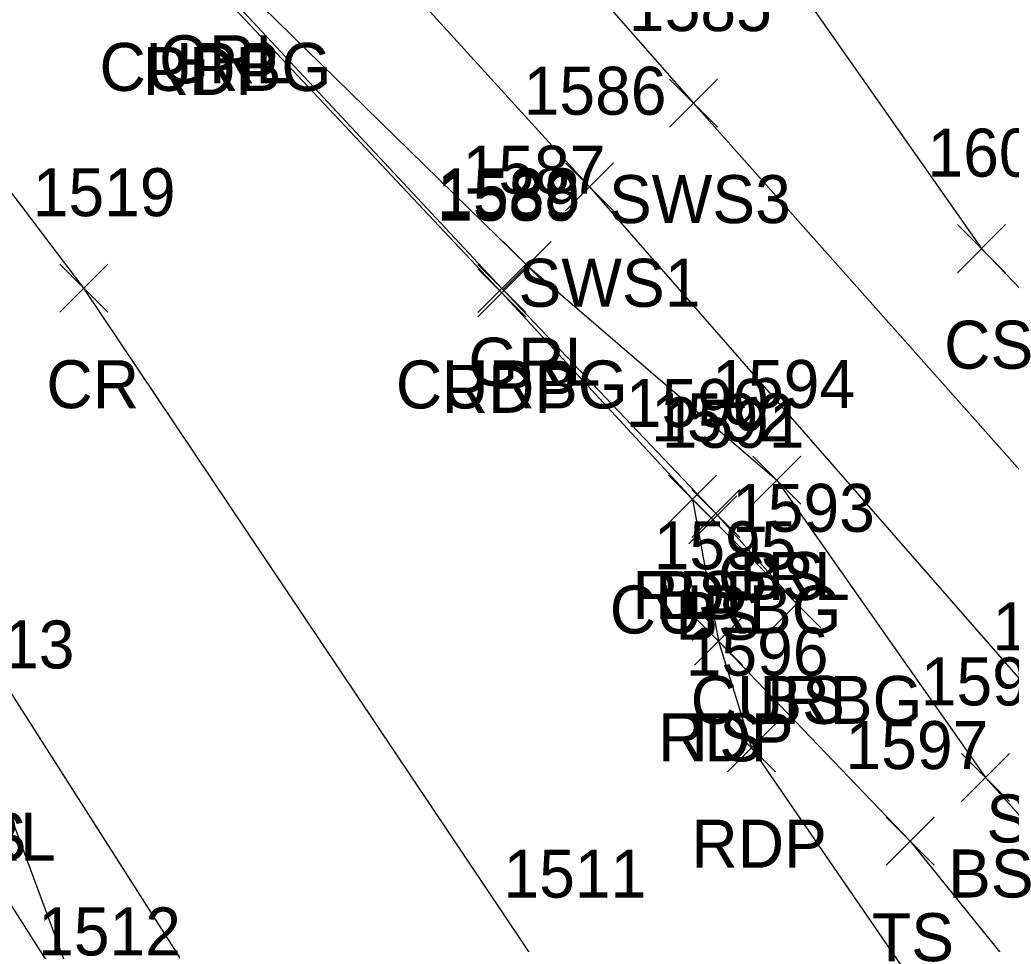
# Model space of a CAD drawing. Extents: x 1499292 to 1501024, y 534584 to 538043.
# Drawn here: x 1499846.53 to 1499887.83, y 537622.77 to 537661.28 of the extents above; entities that cross this region are included whole.
import ezdxf

# ---------------------------------------------------------------- set-up
doc = ezdxf.new("R2010")
doc.units = 0
for name, color, linetype in [('L_A', 7, 'Continuous'), ('L_I', 7, 'Continuous'), ('L_TIC', 7, 'Continuous'), ('LELB', 7, 'Continuous'), ('P_A', 7, 'Continuous'), ('P_I', 7, 'Continuous'), ('P_TIC', 7, 'Continuous'), ('PET', 7, 'Continuous'), ('PRC', 7, 'Continuous'), ('R_A', 7, 'Continuous'), ('R_I', 7, 'Continuous'), ('R_TIC', 7, 'Continuous'), ('RC', 7, 'Continuous'), ('RGR', 7, 'Continuous'), ('RSW', 7, 'Continuous')]:
    doc.layers.add(name, color=color, linetype=linetype)

msp = doc.modelspace()

# ---------------------------------------------------------------- linework, layer by layer
at = {"layer": 'L_TIC'}
for points in [[(1499885.591, 537650.746), (1499887.591, 537652.746)], [(1499887.591, 537650.746), (1499885.591, 537652.746)], [(1499877.067, 537641.108), (1499879.067, 537643.108)], [(1499879.067, 537641.108), (1499877.067, 537643.108)], [(1499873.553, 537640.315), (1499875.553, 537642.315)], [(1499875.553, 537640.315), (1499873.553, 537642.315)], [(1499874.393, 537639.451), (1499876.393, 537641.451)], [(1499876.393, 537639.451), (1499874.393, 537641.451)], [(1499877.892, 537635.949), (1499879.892, 537637.949)], [(1499879.892, 537635.949), (1499877.892, 537637.949)], [(1499874.628, 537634.389), (1499876.628, 537636.389)], [(1499876.628, 537634.389), (1499874.628, 537636.389)], [(1499885.752, 537628.716), (1499887.752, 537630.716)], [(1499887.752, 537628.716), (1499885.752, 537630.716)], [(1499882.617, 537626.063), (1499884.617, 537628.063)], [(1499884.617, 537626.063), (1499882.617, 537628.063)]]:
    msp.add_lwpolyline(points, dxfattribs=at)
at = {"layer": 'LELB'}
for points in [[(1499846.934, 537679.187), (1499854.63, 537681.892), (1499855.345, 537682.192), (1499861.643, 537684.623), (1499869.851, 537675.621), (1499886.591, 537651.746), (1499898.304, 537639.55), (1499906.005, 537630.298), (1499923.982, 537635.989)], [(1499982.952, 537489.682), (1499966.995, 537494.973), (1499951.633, 537501.686), (1499942.165, 537508.923), (1499936.876, 537512.966), (1499930.432, 537522.297), (1499913.696, 537537.042), (1499897.541, 537554.09), (1499883.226, 537576.207), (1499873.982, 537589.177), (1499855.893, 537613.143), (1499849.418, 537619.303), (1499842.663, 537629.916), (1499836.966, 537639.791), (1499825.942, 537654.556), (1499819.306, 537659.466)], [(1499875.628, 537635.389), (1499883.617, 537627.063), (1499893.294, 537615.077), (1499899.95, 537610.946), (1499909.177, 537610.062), (1499915.735, 537611.144), (1499937.582, 537622.682), (1499960.484, 537631.227), (1499993.025, 537642.588), (1500017.771, 537650.353)], [(1499878.067, 537642.108), (1499886.752, 537629.716), (1499900.318, 537614.592), (1499904.837, 537614.724), (1499912.539, 537616.07), (1499937.582, 537622.682)], [(1499874.553, 537641.315), (1499875.393, 537640.451), (1499878.892, 537636.949)]]:
    msp.add_lwpolyline(points, dxfattribs=at)
at = {"layer": 'P_TIC'}
for points in [[(1499848.203, 537649.099), (1499850.203, 537651.099)], [(1499850.203, 537649.099), (1499848.203, 537651.099)], [(1499865.611, 537648.906), (1499867.611, 537650.906)], [(1499867.611, 537648.906), (1499865.611, 537650.906)], [(1499873.553, 537640.315), (1499875.553, 537642.315)], [(1499875.553, 537640.315), (1499873.553, 537642.315)], [(1499874.628, 537634.389), (1499876.628, 537636.389)], [(1499876.628, 537634.389), (1499874.628, 537636.389)], [(1499876.015, 537629.958), (1499878.015, 537631.958)], [(1499878.015, 537629.958), (1499876.015, 537631.958)]]:
    msp.add_lwpolyline(points, dxfattribs=at)
at = {"layer": 'PET'}
msp.add_lwpolyline([(1499898.168, 537558.628), (1499884.724, 537577.025), (1499875.365, 537589.928), (1499858.296, 537614.226), (1499840.479, 537642.142), (1499830.336, 537658.338), (1499824.743, 537665.437), (1499832.024, 537672.415), (1499839.239, 537678.685), (1499843.344, 537674.163), (1499846.686, 537670.947), (1499854.163, 537663.148), (1499866.611, 537649.906), (1499874.553, 537641.315), (1499875.628, 537635.389), (1499877.015, 537630.958), (1499888.962, 537613.552)], dxfattribs=at)
at = {"layer": 'PRC'}
msp.add_lwpolyline([(1500278.962, 537330.133), (1500245.157, 537363.321), (1500217.073, 537386.354), (1500194.782, 537402.066), (1500161.587, 537424.072), (1500124.893, 537444.316), (1500077.396, 537466.829), (1500048.034, 537479.391), (1500024.096, 537489.275), (1500002.859, 537498.228), (1499984.27, 537507.122), (1499965.54, 537516.893), (1499943.097, 537532.261), (1499924.704, 537548.397), (1499906.704, 537567.903), (1499892.971, 537586.047), (1499884.57, 537597.666), (1499868.237, 537621.71), (1499849.203, 537650.099), (1499837.664, 537665.339), (1499832.024, 537672.415)], dxfattribs=at)
at = {"layer": 'R_TIC'}
for points in [[(1499873.596, 537656.81), (1499875.596, 537658.81)], [(1499875.596, 537656.81), (1499873.596, 537658.81)], [(1499869.266, 537653.325), (1499871.266, 537655.325)], [(1499871.266, 537653.325), (1499869.266, 537655.325)], [(1499866.669, 537650.038), (1499868.669, 537652.038)], [(1499868.669, 537650.038), (1499866.669, 537652.038)], [(1499865.612, 537649.088), (1499867.612, 537651.088)], [(1499867.612, 537649.088), (1499865.612, 537651.088)], [(1499877.067, 537641.108), (1499879.067, 537643.108)], [(1499879.067, 537641.108), (1499877.067, 537643.108)], [(1499874.52, 537639.714), (1499876.52, 537641.714)], [(1499876.52, 537639.714), (1499874.52, 537641.714)], [(1499877.892, 537635.949), (1499879.892, 537637.949)], [(1499879.892, 537635.949), (1499877.892, 537637.949)]]:
    msp.add_lwpolyline(points, dxfattribs=at)
at = {"layer": 'RC'}
msp.add_lwpolyline([(1499847.244, 537675.507), (1499847.246, 537676.655), (1499847.125, 537678.118), (1499846.654, 537678.074), (1499847.015, 537671.086), (1499854.266, 537663.317), (1499866.612, 537650.088), (1499875.52, 537640.714), (1499878.892, 537636.949)], dxfattribs=at)
at = {"layer": 'RGR'}
for points in [[(1499839.507, 537678.771), (1499843.62, 537674.746), (1499846.668, 537671.315), (1499847.015, 537671.086), (1499854.787, 537663.633), (1499867.669, 537651.038), (1499878.067, 537642.108)], [(1499849.418, 537619.303), (1499844.983, 537631.257), (1499840.013, 537641.779), (1499824.371, 537665.241)]]:
    msp.add_lwpolyline(points, dxfattribs=at)
at = {"layer": 'RSW'}
for points in [[(1499852.884, 537673.411), (1499857.278, 537677.521), (1499874.596, 537657.81), (1499894.119, 537635.847), (1499912.539, 537616.07), (1499915.735, 537611.144), (1499917.779, 537609.039)], [(1499852.884, 537673.411), (1499870.266, 537654.325), (1499889.752, 537632.008), (1499904.837, 537614.724), (1499909.177, 537610.062), (1499910.819, 537607.885)]]:
    msp.add_lwpolyline(points, dxfattribs=at)

# ---------------------------------------------------------------- texts
at = {"layer": 'L_A'}
for s, p in [('CS', (1499885.032, 537646.746)), ('BS', (1499876.508, 537637.108)), ('BS', (1499872.994, 537636.315)), ('BS', (1499873.834, 537635.451)), ('BS', (1499877.333, 537631.949)), ('TS', (1499874.037, 537630.389)), ('TS', (1499843.392, 537626.257)), ('BS', (1499885.193, 537624.716)), ('TS', (1499882.027, 537622.063))]:
    msp.add_text(s, height=2, dxfattribs=at).set_placement(p)
at = {"layer": 'L_I'}
for s, p in [('1601', (1499884.339, 537654.746)), ('1594', (1499875.374, 537645.108)), ('1590', (1499871.774, 537644.315)), ('1591', (1499873.267, 537643.451)), ('1593', (1499876.199, 537639.949)), ('1595', (1499872.935, 537638.389)), ('1513', (1499842.857, 537634.257)), ('1598', (1499884.059, 537632.716)), ('1597', (1499880.924, 537630.063)), ('1512', (1499847.292, 537622.303))]:
    msp.add_text(s, height=2, dxfattribs=at).set_placement(p)
at = {"layer": 'P_A'}
for s, p in [('RDP', (1499851.651, 537658.148)), ('CR', (1499847.636, 537645.099)), ('RDP', (1499864.099, 537644.906)), ('RDP', (1499872.042, 537636.315)), ('RDP', (1499873.116, 537630.389)), ('RDP', (1499874.503, 537625.958))]:
    msp.add_text(s, height=2, dxfattribs=at).set_placement(p)
at = {"layer": 'P_I'}
for s, p in [('1519', (1499847.069, 537653.099)), ('1589', (1499863.91, 537652.906)), ('1590', (1499871.774, 537644.315)), ('1595', (1499872.935, 537638.389)), ('1596', (1499874.267, 537633.958)), ('1511', (1499866.678, 537624.71))]:
    msp.add_text(s, height=2, dxfattribs=at).set_placement(p)
at = {"layer": 'R_A'}
for s, p in [('CURBG', (1499849.849, 537658.317)), ('GRL', (1499852.33, 537658.633)), ('SWS3', (1499871.068, 537652.81)), ('SWS1', (1499867.305, 537649.325)), ('GRL', (1499865.212, 537646.038)), ('CURBG', (1499862.194, 537645.088)), ('GRL', (1499875.61, 537637.108)), ('CURBG', (1499871.103, 537635.714)), ('CURBG', (1499874.475, 537631.949)), ('SWS1', (1499886.791, 537627.008)), ('GRL', (1499842.526, 537626.257))]:
    msp.add_text(s, height=2, dxfattribs=at).set_placement(p)
at = {"layer": 'R_I'}
for s, p in [('1585', (1499871.903, 537660.81)), ('1586', (1499867.518, 537657.325)), ('1587', (1499864.976, 537654.038)), ('1588', (1499863.919, 537653.088)), ('1594', (1499875.374, 537645.108)), ('1592', (1499872.827, 537643.714)), ('1593', (1499876.199, 537639.949)), ('1599', (1499887.051, 537635.008)), ('1513', (1499842.857, 537634.257)), ('1512', (1499847.292, 537622.303))]:
    msp.add_text(s, height=2, dxfattribs=at).set_placement(p)

doc.saveas('drawing.dxf')
